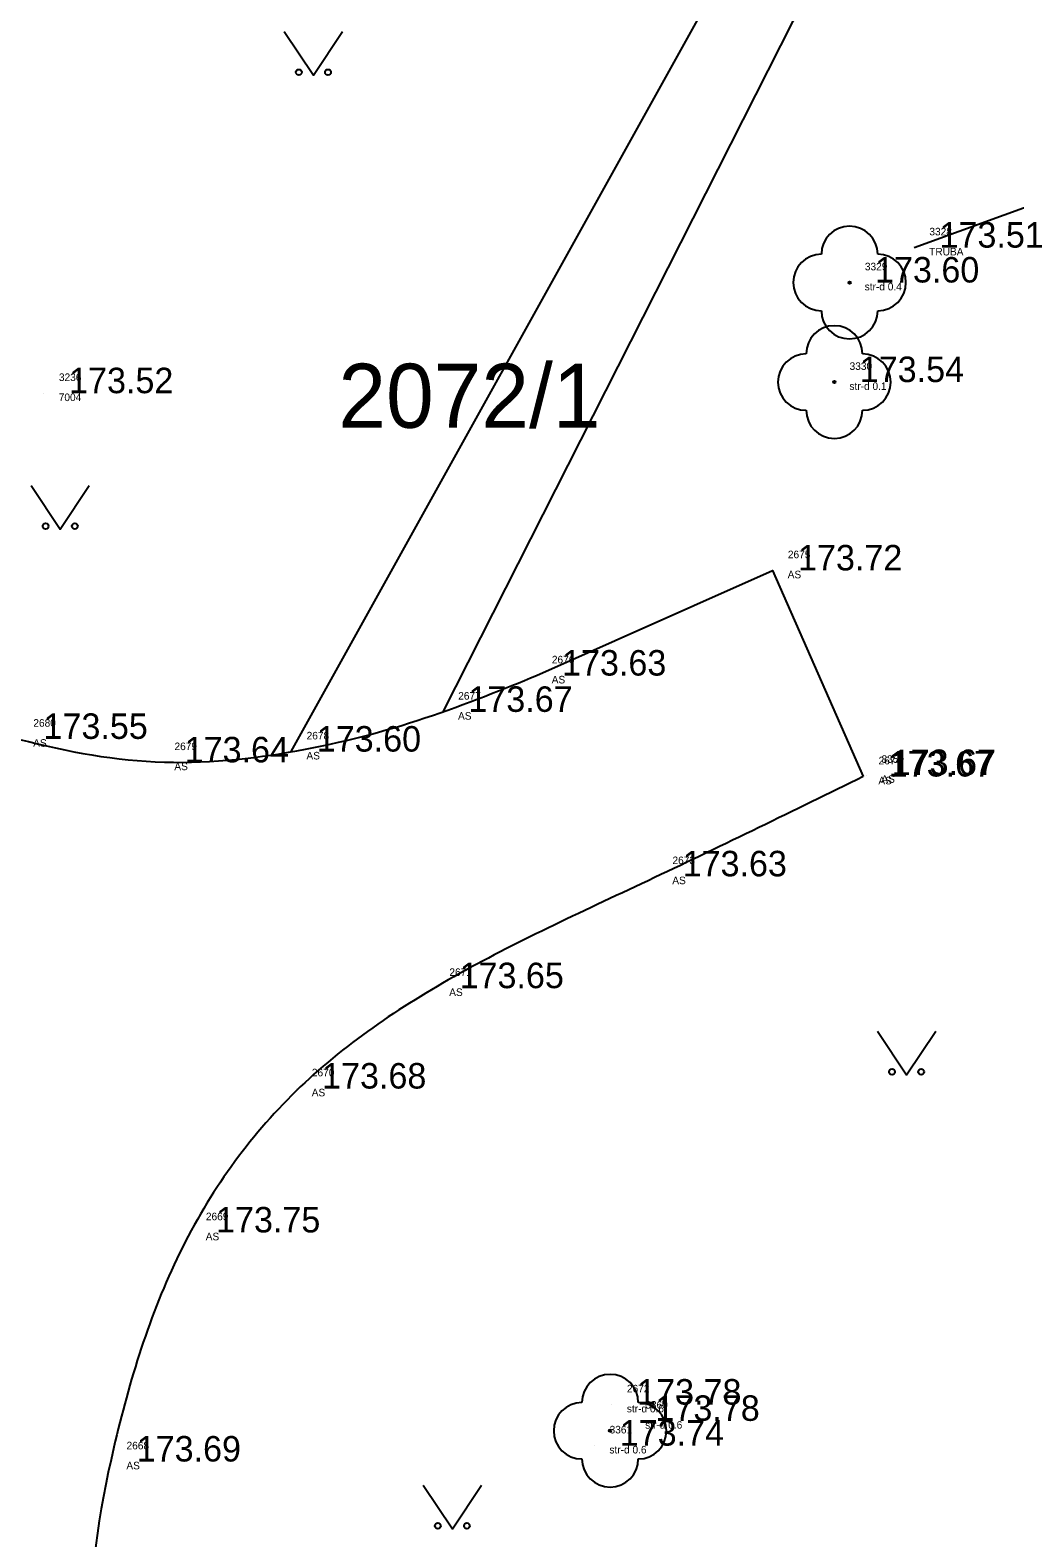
# Model space of a CAD drawing. Extents: x -566117 to -565580, y -1202428 to -1201938.
# Drawn here: x -565686.57 to -565669.67, y -1202093.76 to -1202067.88 of the extents above; entities that cross this region are included whole.
import ezdxf

# ---------------------------------------------------------------- set-up
doc = ezdxf.new("R2010")
doc.units = 0
for name, color, linetype in [('Bod', 7, 'Continuous'), ('Implicitní', 7, 'Continuous'), ('Katastr', 7, 'Continuous'), ('Kod', 7, 'Continuous'), ('Výška', 7, 'Continuous'), ('ZELEŇ', 7, 'Continuous'), ('ZN_KULTUR', 7, 'Continuous'), ('Zpevněné plohy', 7, 'Continuous'), ('Číslo', 7, 'Continuous')]:
    doc.layers.add(name, color=color, linetype=linetype)

# ---------------------------------------------------------------- blocks, each defined once
blk = doc.blocks.new('A$C69D74C1E')
at = {"layer": 'Katastr'}
blk.add_text('2072/1', height=1.1, dxfattribs=at).set_placement((383.65, -6.263))
blk = doc.blocks.new('POINT_DISPLAY')
at = {"layer": 'Implicitní'}
blk.add_line((0, 0), (0, 0), dxfattribs=at)
blk = doc.blocks.new('3$13')
at = {"layer": 'ZELEŇ'}
blk.add_circle((0, 0), 0.02, dxfattribs=at)
for centre, start, end in [((0.000055, 0.484), 0, 179.9999972), ((-0.483945, 0), 90, 269.9999972), ((0.484055, 0), 270, 89.9999972), ((0.000055, -0.484), 180.0000028, 0)]:
    blk.add_arc(centre, 0.484, start, end, dxfattribs=at)
blk.add_blockref('POINT_DISPLAY', (0, 0), dxfattribs=at)
blk = doc.blocks.new('3.140_2')
at = {"layer": 'ZN_KULTUR'}
blk.add_lwpolyline([(-1, 1.5), (0, 0), (1, 1.5)], dxfattribs=at)
for centre in [(-0.5, 0.1), (0.5, 0.1)]:
    blk.add_circle(centre, 0.1, dxfattribs=at)

msp = doc.modelspace()

# ---------------------------------------------------------------- linework, layer by layer
at = {"layer": 'Implicitní'}
msp.add_line((-565671.398, -1202071.61), (-565668.543, -1202070.568), dxfattribs=at)
at = {"layer": 'Zpevněné plohy'}
for p, q in [((-565682.089, -1202080.261), (-565674.537, -1202066.661)), ((-565673.163, -1202067.1), (-565679.487, -1202079.579))]:
    msp.add_line(p, q, dxfattribs=at)
msp.add_lwpolyline([(-565677.879, -1202078.956), (-565673.828, -1202077.151), (-565672.27, -1202080.689)], dxfattribs=at)
for points in [[(-565694.915, -1202073.202), (-565694.6, -1202073.879), (-565693.798, -1202075.599), (-565691.834, -1202077.578), (-565689.401, -1202079.237), (-565686.913, -1202080.065), (-565684.423, -1202080.564), (-565681.938, -1202080.298), (-565679.776, -1202079.727), (-565678.411, -1202079.173), (-565677.879, -1202078.956)], [(-565672.27, -1202080.689), (-565673.447, -1202081.266), (-565675.906, -1202082.471), (-565679.286, -1202084.003), (-565682.155, -1202085.946), (-565684.164, -1202088.764), (-565685.227, -1202092.222), (-565685.742, -1202095.569), (-565685.196, -1202097.417), (-565684.992, -1202098.109)], [(-565664.348, -1202093.299), (-565664.353, -1202093.299), (-565665.183, -1202093.292), (-565667.324, -1202093.607), (-565670.746, -1202094.344), (-565674.751, -1202095.63), (-565677.672, -1202096.819), (-565679.625, -1202097.604), (-565680.849, -1202098.338), (-565681.779, -1202099.49), (-565683.292, -1202099.811), (-565683.967, -1202099.76), (-565684.411, -1202099.727)]]:
    msp.add_open_spline(points, degree=3, dxfattribs=at)

# ---------------------------------------------------------------- block references
at = {"layer": 'Bod'}
for p in [(-565671.398, -1202071.61), (-565672.506, -1202072.209), (-565672.767, -1202073.918), (-565686.34, -1202074.109), (-565673.828, -1202077.151), (-565677.879, -1202078.956), (-565679.487, -1202079.579), (-565684.356, -1202080.446), (-565682.089, -1202080.261), (-565672.27, -1202080.689), (-565672.219, -1202080.663), (-565675.809, -1202082.402), (-565679.637, -1202084.322), (-565681.998, -1202086.045), (-565683.818, -1202088.515), (-565676.589, -1202091.47), (-565676.275, -1202091.749), (-565676.888, -1202092.174), (-565685.18, -1202092.447)]:
    msp.add_blockref('POINT_DISPLAY', p, dxfattribs=at)
at = {"layer": 'Implicitní'}
msp.add_blockref('A$C69D74C1E', (-566064.93, -1202068.44), dxfattribs=at)
at = {"layer": 'ZELEŇ'}
for p in [(-565672.506, -1202072.209), (-565672.767, -1202073.918), (-565676.616, -1202091.919)]:
    msp.add_blockref('3$13', p, dxfattribs=at)
at = {"layer": 'ZN_KULTUR', "xscale": 0.5, "yscale": 0.5}
for p in [(-565681.709, -1202068.65), (-565686.056, -1202076.441), (-565671.527, -1202085.808), (-565679.324, -1202093.601)]:
    msp.add_blockref('3.140_2', p, dxfattribs=at)

# ---------------------------------------------------------------- texts
at = {"layer": 'Kod'}
for s, p in [('TRUBA', (-565671.139, -1202071.744)), ('str-d 0.4', (-565672.246, -1202072.344)), ('str-d 0.1', (-565672.508, -1202074.053)), ('7004', (-565686.081, -1202074.244)), ('AS', (-565673.568, -1202077.286)), ('AS', (-565677.619, -1202079.091)), ('AS', (-565679.227, -1202079.713)), ('AS', (-565686.52, -1202080.178)), ('AS', (-565684.097, -1202080.58)), ('AS', (-565681.829, -1202080.396)), ('AS', (-565672.011, -1202080.824)), ('AS', (-565671.96, -1202080.798)), ('AS', (-565675.549, -1202082.537)), ('AS', (-565679.378, -1202084.456)), ('AS', (-565681.738, -1202086.179)), ('AS', (-565683.558, -1202088.65)), ('str-d 0.6', (-565676.329, -1202091.604)), ('str-d 0.6', (-565676.015, -1202091.883)), ('str-d 0.6', (-565676.628, -1202092.309)), ('AS', (-565684.92, -1202092.582))]:
    msp.add_text(s, height=0.13, dxfattribs=at).set_placement(p)
at = {"layer": 'Výška'}
for s, p in [('173.51', (-565670.961, -1202071.61)), ('173.60', (-565672.068, -1202072.209)), ('173.54', (-565672.33, -1202073.918)), ('173.52', (-565685.903, -1202074.109)), ('173.72', (-565673.39, -1202077.151)), ('173.63', (-565677.441, -1202078.956)), ('173.67', (-565679.049, -1202079.579)), ('173.55', (-565686.342, -1202080.043)), ('173.60', (-565681.651, -1202080.261)), ('173.64', (-565683.919, -1202080.446)), ('173.67', (-565671.833, -1202080.689)), ('173.67', (-565671.782, -1202080.663)), ('173.63', (-565675.371, -1202082.402)), ('173.65', (-565679.2, -1202084.322)), ('173.68', (-565681.56, -1202086.045)), ('173.75', (-565683.38, -1202088.515)), ('173.78', (-565676.151, -1202091.47)), ('173.78', (-565675.837, -1202091.749)), ('173.74', (-565676.45, -1202092.174)), ('173.69', (-565684.742, -1202092.447))]:
    msp.add_text(s, height=0.4375, dxfattribs=at).set_placement(p)
at = {"layer": 'Číslo'}
for s, p in [('3328', (-565671.136, -1202071.4)), ('3329', (-565672.243, -1202072)), ('3236', (-565686.078, -1202073.9)), ('3330', (-565672.505, -1202073.709)), ('2675', (-565673.565, -1202076.942)), ('2676', (-565677.616, -1202078.747)), ('2677', (-565679.224, -1202079.369)), ('2680', (-565686.517, -1202079.834)), ('2678', (-565681.826, -1202080.052)), ('2679', (-565684.094, -1202080.236)), ('2674', (-565672.008, -1202080.48)), ('3359', (-565671.957, -1202080.454)), ('2673', (-565675.546, -1202082.193)), ('2671', (-565679.375, -1202084.112)), ('2670', (-565681.736, -1202085.835)), ('2669', (-565683.555, -1202088.306)), ('2672', (-565676.327, -1202091.26)), ('3360', (-565676.012, -1202091.539)), ('3361', (-565676.625, -1202091.965)), ('2668', (-565684.917, -1202092.238))]:
    msp.add_text(s, height=0.13, dxfattribs=at).set_placement(p)

doc.saveas('drawing.dxf')
